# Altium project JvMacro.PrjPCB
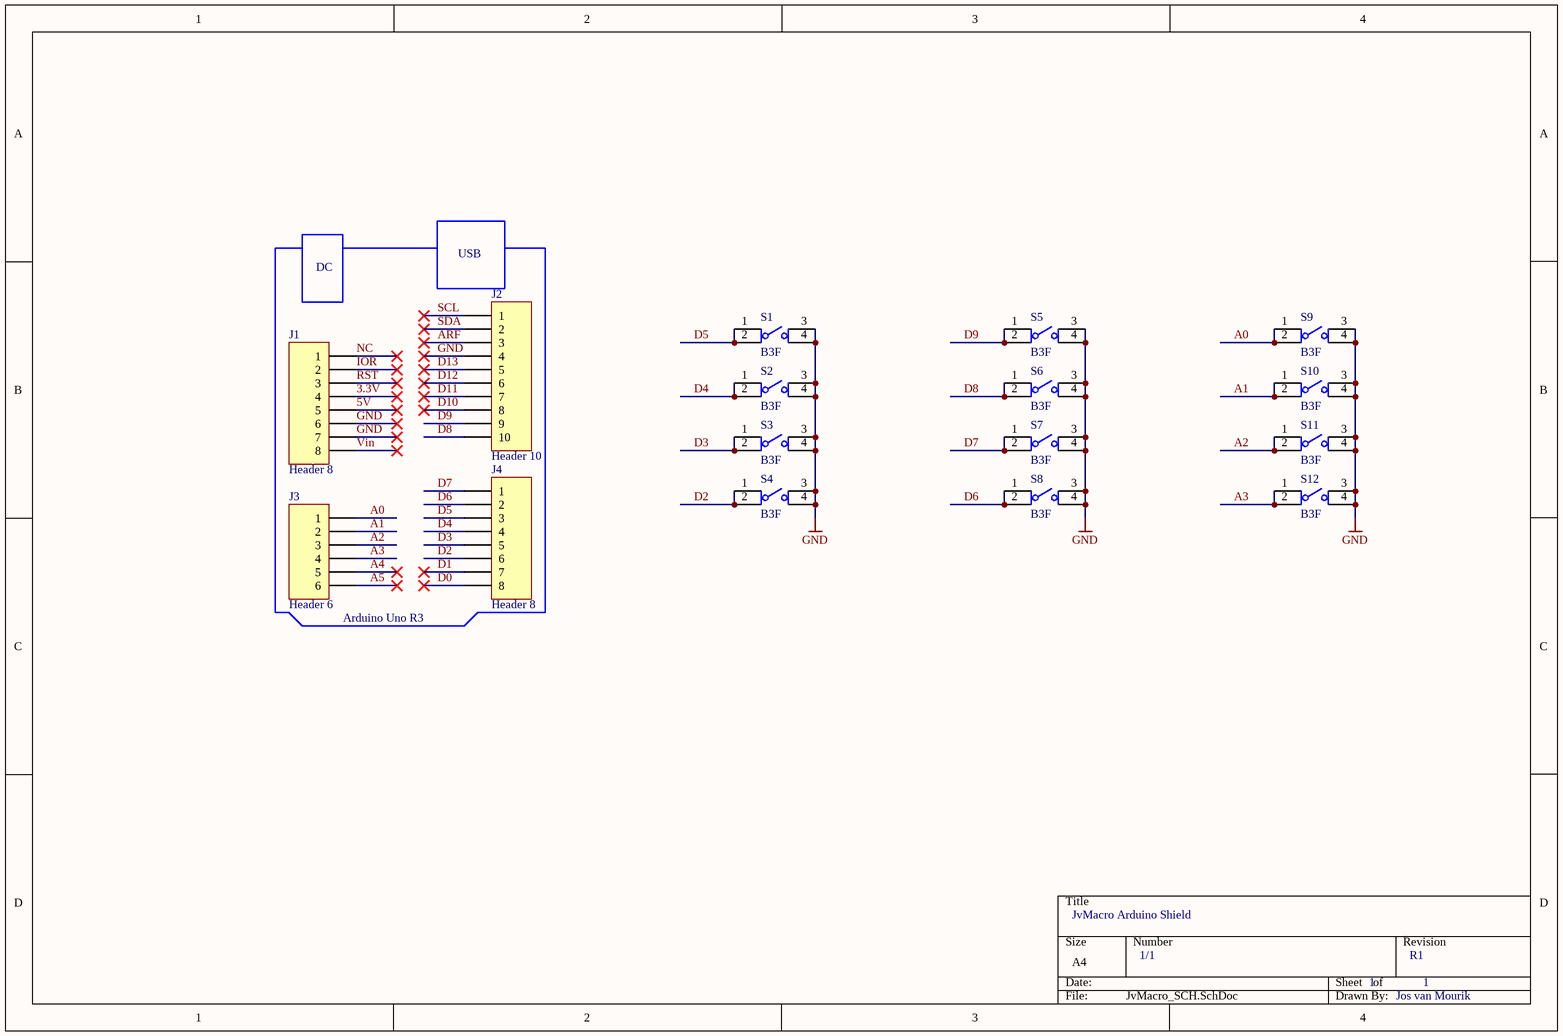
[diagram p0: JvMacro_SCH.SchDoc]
1 sheet, 16 parts. Net scope: global (net labels, ports and power ports of the same name join across sheets).
Board file: JvMacro_PCB.PcbDoc

## Sheet JvMacro_SCH.SchDoc
size A4

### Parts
J1  Header 8  [HDR1X8]
J2  Header 10  [HDR1X10]
J3  Header 6  [HDR1X6]
J4  Header 8  [HDR1X8]
S1  B3F  [Omron_B3F-4055]
S2  B3F  [Omron_B3F-4055]
S3  B3F  [Omron_B3F-4055]
S4  B3F  [Omron_B3F-4055]
S5  B3F  [Omron_B3F-4055]
S6  B3F  [Omron_B3F-4055]
S7  B3F  [Omron_B3F-4055]
S8  B3F  [Omron_B3F-4055]
S9  B3F  [Omron_B3F-4055]
S10  B3F  [Omron_B3F-4055]
S11  B3F  [Omron_B3F-4055]
S12  B3F  [Omron_B3F-4055]

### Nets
GND: J1.6 J1.7 J2.4 S1.3 S1.4 S2.3 S2.4 S3.3 S3.4 S4.3 S4.4 S5.3 S5.4 S6.3 S6.4 S7.3 S7.4 S8.3 S8.4 S9.3 S9.4 S10.3 S10.4 S11.3 S11.4 S12.3 S12.4
3.3V: J1.4
5V: J1.5
A0: J3.1 S9.1 S9.2
A1: J3.2 S10.1 S10.2
A2: J3.3 S11.1 S11.2
A3: J3.4 S12.1 S12.2
A4: J3.5
A5: J3.6
ARF: J2.3
D0: J4.8
D1: J4.7
D2: J4.6 S4.1 S4.2
D3: J4.5 S3.1 S3.2
D4: J4.4 S2.1 S2.2
D5: J4.3 S1.1 S1.2
D6: J4.2 S8.1 S8.2
D7: J4.1 S7.1 S7.2
D8: J2.10 S6.1 S6.2
D9: J2.9 S5.1 S5.2
D10: J2.8
D11: J2.7
D12: J2.6
D13: J2.5
IOR: J1.2
NC: J1.1
RST: J1.3
SCL: J2.1
SDA: J2.2
Vin: J1.8

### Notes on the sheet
- DC
- USB
- (near J3) Arduino Uno R3
- JvMacro Arduino Shield
- 1/1
- 1
- R1
- Jos van Mourik

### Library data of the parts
J1 J4 = Header 8: 2,54mm pitch header, 8 positions; Pitch: 2.54mm
J2 = Header 10: 2,54mm pitch header, 10 positions; Pitch: 2.54mm
J3 = Header 6: 2,54mm pitch header, 6 positions; Pitch: 2.54mm
S1-S12 = B3F-4055: B3F pushbutton, 12x12mm, through hole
